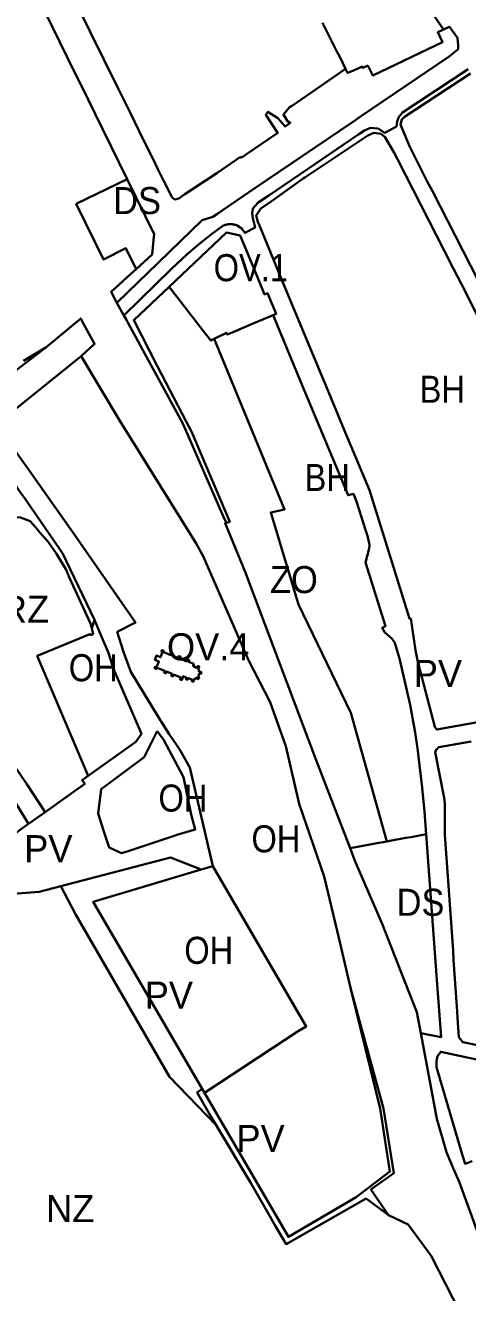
# Model space of a CAD drawing. Extents: x -650451 to -642268, y -1075216 to -1066610.
# Drawn here: x -647596 to -647351, y -1071706 to -1071004 of the extents above; entities that cross this region are included whole.
import ezdxf

# ---------------------------------------------------------------- set-up
doc = ezdxf.new("R2010")
doc.units = 0
doc.header["$LTSCALE"] = 6
doc.layers.add('1', color=7, linetype='Continuous', lineweight=35)
doc.layers.add('2', color=7, linetype='Continuous')
doc.layers.add('3', color=7, linetype='Continuous')

msp = doc.modelspace()

# ---------------------------------------------------------------- linework, layer by layer
at = {"layer": '1'}
for p, q in [((-647545.47, -1071157.86), (-647541.66, -1071164.75)), ((-647584.92, -1071182.54), (-647597.164, -1071189.857)), ((-647557.95, -1071333.44), (-647559.45, -1071338.18)), ((-647594.43, -1071446.543), (-647585.273, -1071440.044)), ((-647492.3, -1071470), (-647498.8, -1071471.94)), ((-647498.271, -1071593.544), (-647497.04, -1071595.66))]:
    msp.add_line(p, q, dxfattribs=at)
for points in [[(-647715.3, -1070769.09), (-647708.31, -1070783.21), (-647708.04, -1070783.07), (-647706.21, -1070786.87), (-647704.498, -1070790.24), (-647705.06, -1070790.51), (-647701.56, -1070797.79), (-647701.32, -1070798.28), (-647701.41, -1070798.33), (-647694.09, -1070813.56), (-647693.96, -1070813.49), (-647689.95, -1070821.13), (-647689.08, -1070820.64), (-647686.2, -1070826.54), (-647687.12, -1070826.94), (-647681.06, -1070839.75), (-647660.03, -1070856.69), (-647649.83, -1070864.82), (-647638.54, -1070887.82), (-647572.64, -1071022.41), (-647567.83, -1071032.07), (-647565.56, -1071036.69), (-647553.4, -1071061.35), (-647539.817, -1071089.199)], [(-647380.69, -1070978.37), (-647374.95, -1070991.15), (-647364.66, -1071006.25)], [(-647418.88, -1071028.01), (-647432.19, -1071037.23), (-647448.32, -1071048.39), (-647449.88, -1071049.31), (-647453.32, -1071053.37), (-647451.07, -1071057.07), (-647449.5, -1071057.92), (-647452.4, -1071060.03), (-647456.45, -1071055.44), (-647461.89, -1071051.91), (-647463.11, -1071053.53), (-647456.74, -1071063.18), (-647456.46, -1071063.6), (-647474.29, -1071075.65), (-647476.74, -1071077.3), (-647477.02, -1071076.88), (-647484.83, -1071082.15), (-647490.23, -1071085.8), (-647495.99, -1071089.71), (-647507.93, -1071097.59), (-647511.17, -1071099.94), (-647511.87, -1071100.11), (-647513.3, -1071100.42), (-647514.56, -1071099.74), (-647515.13, -1071098.97), (-647519.54, -1071090.25), (-647522.86, -1071083.58), (-647524.21, -1071080.84), (-647528.95, -1071071.14), (-647530.69, -1071067.54), (-647538.23, -1071052.19), (-647544.95, -1071038.52), (-647560.28, -1071007.46), (-647569.19, -1070989.36)], [(-647545.47, -1071157.86), (-647522.5, -1071135.41), (-647498.37, -1071111.95), (-647492.4, -1071110.08), (-647489.86, -1071108.38), (-647486.58, -1071106.19), (-647469.06, -1071094.28), (-647415.14, -1071057.61), (-647410.1, -1071054.18), (-647392.4, -1071042.15), (-647361.56, -1071021.28), (-647356.62, -1071017.06), (-647356.47, -1071014.98), (-647356.96, -1071010.82), (-647361.42, -1071004.71), (-647364.66, -1071006.25)], [(-647431.74, -1071002.56), (-647423.84, -1071018.04), (-647421.89, -1071021.82), (-647418.88, -1071028.01)], [(-647364.66, -1071006.25), (-647367.88, -1071007.78), (-647365.21, -1071013.19), (-647403.85, -1071031.66), (-647406.65, -1071026.24), (-647409.36, -1071027.52), (-647409.68, -1071026.85), (-647411.52, -1071027.64), (-647415.84, -1071029.49), (-647417.76, -1071030.31), (-647418.88, -1071028.01)], [(-647541.66, -1071164.75), (-647515.26, -1071138.89), (-647506.78, -1071130.92), (-647500.44, -1071125.54), (-647493.16, -1071119.77), (-647486.76, -1071115.13), (-647486, -1071114.76), (-647485.58, -1071114.61), (-647485.149, -1071114.479), (-647484.709, -1071114.368), (-647484.262, -1071114.278), (-647483.809, -1071114.209), (-647483.352, -1071114.162), (-647482.892, -1071114.138), (-647482.43, -1071114.137), (-647481.969, -1071114.158), (-647481.51, -1071114.201), (-647481.055, -1071114.267), (-647480.605, -1071114.355), (-647480.163, -1071114.464), (-647479.728, -1071114.593), (-647479.304, -1071114.742), (-647478.89, -1071114.91), (-647476.29, -1071116.6), (-647474.6, -1071119.05), (-647468.9, -1071115.97), (-647470.21, -1071110.77), (-647470.6, -1071108.01), (-647470.17, -1071105.39), (-647467.21, -1071102.22), (-647461.39, -1071098.23), (-647444.01, -1071086.37), (-647411.59, -1071064.32), (-647408.48, -1071062.15), (-647405.08, -1071060.75), (-647400.89, -1071061.05), (-647397.82, -1071063.08), (-647397.17, -1071063.56), (-647390.72, -1071059.94), (-647390.34, -1071057.27), (-647389.59, -1071055.1), (-647387.4, -1071052.29), (-647350.96, -1071028.22)], [(-647349.67, -1071030.64), (-647386.3, -1071054.58), (-647387.82, -1071056.14), (-647388.51, -1071058.82), (-647383.43, -1071070.95), (-647373.86, -1071090.07), (-647370.76, -1071095.88), (-647316.07, -1071202.91)], [(-647345.67, -1071390.27), (-647368.38, -1071394.35), (-647369.51, -1071392.87), (-647378.79, -1071356.84), (-647380.17, -1071350.38), (-647382.83, -1071332.82), (-647383.52, -1071332.79), (-647405.59, -1071261.54), (-647419.59, -1071228.11), (-647430.16, -1071202.64), (-647431.77, -1071198.79), (-647454.33, -1071144.64), (-647466.6, -1071114.88), (-647467.47, -1071112.93), (-647468.47, -1071109.42), (-647465.83, -1071105.54), (-647460.06, -1071101.57), (-647442.36, -1071088.82), (-647441.42, -1071088.2), (-647406.52, -1071065.05), (-647403.15, -1071063.6), (-647399.31, -1071064.09), (-647397.07, -1071065.71), (-647392.21, -1071074.16), (-647389.98, -1071078.54), (-647364.3, -1071128.77), (-647359.04, -1071138.83), (-647354.68, -1071147.49), (-647339.01, -1071178.6)], [(-647534.851, -1071139.015), (-647540.48, -1071127.55), (-647553.01, -1071133.68), (-647568.01, -1071102.98), (-647539.817, -1071089.199)], [(-647534.851, -1071139.015), (-647526.04, -1071130.94), (-647525.1, -1071121.25), (-647524.95, -1071119.68), (-647539.817, -1071089.199)], [(-647516.65, -1071148.87), (-647484.84, -1071118.8), (-647477.3, -1071120.38), (-647469.39, -1071139.47), (-647463.76, -1071153.08), (-647462.13, -1071152.39), (-647457.39, -1071163.94), (-647458.99, -1071164.62)], [(-647545.47, -1071157.86), (-647548.7, -1071151.72), (-647538.02, -1071141.92), (-647534.851, -1071139.015)], [(-647484.9, -1071279.73), (-647483.04, -1071279.11), (-647504.27, -1071229.17), (-647507.14, -1071223.62), (-647523.09, -1071193.08), (-647536.2, -1071167.35), (-647516.65, -1071148.87)], [(-647491.56, -1071177.65), (-647493.58, -1071178.64), (-647497.03, -1071174.18), (-647516.65, -1071148.87)], [(-647584.92, -1071182.54), (-647565.54, -1071166.39), (-647564.11, -1071169.03), (-647559.87, -1071176.88), (-647557.9, -1071180.51), (-647565.22, -1071187.4)], [(-647541.66, -1071164.75), (-647540.27, -1071167.26), (-647539.25, -1071169.11), (-647508.98, -1071224.74), (-647485.9, -1071277.7), (-647484.9, -1071279.73)], [(-647458.99, -1071164.62), (-647469.69, -1071169.11), (-647475.25, -1071171.44), (-647480.78, -1071173.77), (-647484.47, -1071175.32), (-647484.85, -1071174.37), (-647491.56, -1071177.65)], [(-647458.99, -1071164.62), (-647443.1, -1071203.11), (-647417.48, -1071264.44), (-647414.45, -1071263.72), (-647412.92, -1071267.86), (-647407.95, -1071282.98), (-647406.83, -1071286.84), (-647405.81, -1071290.99), (-647405.67, -1071292.42), (-647405.81, -1071293.71), (-647406, -1071294.73), (-647407.77, -1071301.63), (-647396.78, -1071337.03), (-647398.69, -1071338), (-647397.07, -1071340.54), (-647393.18, -1071343.93), (-647391.57, -1071346.17), (-647389.7, -1071352.48), (-647389.02, -1071354.89), (-647383.11, -1071380.7), (-647381.2, -1071391.04), (-647380.88, -1071392.81), (-647380.41, -1071395.94), (-647378.88, -1071406.02), (-647378.64, -1071407.86), (-647376.66, -1071424.88), (-647376.42, -1071426.67), (-647375.13, -1071439.72), (-647374.2, -1071452.36)], [(-647668.226, -1071237.57), (-647661.99, -1071236.62), (-647658.78, -1071235.63), (-647651.93, -1071233.57), (-647635.17, -1071224.18), (-647613.09, -1071204.33), (-647610.4, -1071201.91), (-647584.92, -1071182.54)], [(-647396.02, -1071456.32), (-647415.97, -1071385.01), (-647445, -1071324.99), (-647460.28, -1071274.02), (-647452.69, -1071272.32), (-647491.56, -1071177.65)], [(-647605.5, -1071220.17), (-647603.35, -1071218), (-647565.22, -1071187.4)], [(-647416, -1071538.22), (-647422.68, -1071509.72), (-647430.76, -1071475.77), (-647444.55, -1071435.57), (-647451.96, -1071403.5), (-647460.71, -1071379.08), (-647472.58, -1071355.91), (-647487.02, -1071322.83), (-647497.77, -1071298.19), (-647501.59, -1071291.15), (-647504.01, -1071287.34), (-647543.83, -1071223.23), (-647565.22, -1071187.4)], [(-647605.5, -1071220.17), (-647607.11, -1071222.78), (-647608.04, -1071225.7), (-647608.09, -1071228.7), (-647607.49, -1071231.68), (-647592.65, -1071252.72), (-647568.83, -1071286.51), (-647535.19, -1071335), (-647545.42, -1071340.16), (-647542.01, -1071350.72), (-647541.66, -1071351.76), (-647537.84, -1071362.41), (-647521.32, -1071389.29), (-647521.06, -1071389.76), (-647516.55, -1071396.79), (-647510.84, -1071405.24), (-647505.11, -1071415.37), (-647492.3, -1071470)], [(-647557.95, -1071333.44), (-647575.61, -1071296.52), (-647596.91, -1071265.68), (-647598.99, -1071262.68), (-647600.93, -1071259.86), (-647601.37, -1071259.23), (-647604.8, -1071254.95), (-647607.21, -1071251.94), (-647611.46, -1071246.64), (-647611.07, -1071246.43), (-647612.8, -1071244.96), (-647620.21, -1071238.7), (-647626.92, -1071241.32), (-647628.88, -1071242.01), (-647629.84, -1071242.36), (-647640.98, -1071246.3), (-647646.11, -1071248.11), (-647651.83, -1071250.14), (-647662.68, -1071253.98), (-647673.55, -1071257.83), (-647679.2, -1071259.81), (-647680.57, -1071260.28), (-647689.61, -1071263.51)], [(-647559.45, -1071338.18), (-647560.08, -1071335.6), (-647565.43, -1071323.92), (-647571.68, -1071310.25), (-647573.87, -1071305.47), (-647578.87, -1071296.87), (-647583.66, -1071290.33), (-647588.2, -1071285.06), (-647590.57, -1071282.13), (-647593.59, -1071278.74), (-647598.84, -1071276.77), (-647601.82, -1071276.61), (-647607.25, -1071278.65), (-647621.64, -1071294.26), (-647642.12, -1071312.63), (-647645.94, -1071311.85), (-647653.22, -1071310.36), (-647660.39, -1071318.38), (-647666.629, -1071325.351)], [(-647484.9, -1071279.73), (-647485.58, -1071279.95), (-647474.15, -1071307.9), (-647471.19, -1071315.76), (-647435.19, -1071411.22), (-647416.42, -1071460.03)], [(-647557.95, -1071333.44), (-647554.18, -1071342.3), (-647550.12, -1071351.87), (-647547.43, -1071360.71), (-647531.93, -1071396.68), (-647534.94, -1071401.09), (-647561.38, -1071419.94)], [(-647559.45, -1071338.18), (-647558.66, -1071341.37), (-647560.16, -1071341.99), (-647560.46, -1071341.39), (-647589.03, -1071353.19), (-647589.57, -1071353.41), (-647561.38, -1071419.94)], [(-647701.415, -1071480.15), (-647699.767, -1071481.617), (-647625.428, -1071403.267), (-647612.269, -1071419.742), (-647605.292, -1071428.816), (-647594.43, -1071446.543)], [(-647335.88, -1071571.31), (-647353.95, -1071567.53), (-647356.2, -1071564.75), (-647356.91, -1071554.11), (-647357.15, -1071550.44), (-647359.03, -1071522.12), (-647359.38, -1071516.88), (-647363.86, -1071452.66), (-647363.83, -1071435.52), (-647364.26, -1071432.14), (-647369.34, -1071406.92), (-647368.74, -1071405.48), (-647367.18, -1071404.12), (-647349.29, -1071400.99)], [(-647585.273, -1071440.044), (-647595.335, -1071424.564), (-647603.9, -1071412.1)], [(-647585.273, -1071440.044), (-647572.79, -1071431.18), (-647563.33, -1071424.47), (-647564.81, -1071422.45), (-647561.38, -1071419.94)], [(-647594.43, -1071446.543), (-647597.54, -1071448.75), (-647611.82, -1071459.38), (-647626.7, -1071470.46), (-647642.45, -1071482.62), (-647655.517, -1071492.465), (-647656.27, -1071493.04), (-647674.28, -1071506.59), (-647676.51, -1071504.34), (-647764.23, -1071571.01), (-647771.717, -1071576.551)], [(-647416.42, -1071460.03), (-647412.36, -1071459.29), (-647409.26, -1071458.73), (-647403.35, -1071457.65), (-647400.4, -1071457.12), (-647398.057, -1071456.69), (-647396.02, -1071456.32)], [(-647374.2, -1071452.36), (-647379.73, -1071453.36), (-647382.59, -1071453.88), (-647385.49, -1071454.41), (-647388.54, -1071454.96), (-647394.45, -1071456.04), (-647396.02, -1071456.32)], [(-647374.2, -1071452.36), (-647368.26, -1071532.99), (-647365.91, -1071564.81), (-647377.13, -1071562.56)], [(-647377.13, -1071562.56), (-647379.49, -1071550.89), (-647388.29, -1071528.41), (-647398.64, -1071501.96), (-647413.54, -1071467.53), (-647416.42, -1071460.03)], [(-647498.8, -1071471.94), (-647515.87, -1071465.25), (-647576.471, -1071481.091)], [(-647497.04, -1071595.66), (-647445.11, -1071561.48), (-647440.67, -1071558.93), (-647492.3, -1071470)], [(-647498.271, -1071593.544), (-647558.654, -1071489.738), (-647498.8, -1071471.94)], [(-647576.471, -1071481.091), (-647588.48, -1071484.23), (-647632, -1071487.54), (-647639.66, -1071490.78), (-647650.97, -1071499.11), (-647658.2, -1071504.43), (-647694.65, -1071531.5), (-647756.17, -1071577.89), (-647767.07, -1071589.67), (-647771.408, -1071602.414)], [(-647576.471, -1071481.091), (-647568.35, -1071496.656), (-647516.376, -1071586.89), (-647490.561, -1071613.609)], [(-647497.04, -1071595.66), (-647450.58, -1071675.53), (-647413.06, -1071653.58), (-647394.33, -1071639.33), (-647399.81, -1071604.31), (-647416, -1071538.22)], [(-647395.07, -1071663.45), (-647404.81, -1071649.36), (-647392.2, -1071640.14), (-647397.94, -1071604.35), (-647416, -1071538.22)], [(-647286.89, -1071767.67), (-647288.23, -1071768.15), (-647312.86, -1071737.11), (-647344.03, -1071677.91), (-647355.85, -1071645.37), (-647359.23, -1071637.45), (-647363.05, -1071628.52), (-647368.43, -1071610.03), (-647375.33, -1071572.37), (-647377.13, -1071562.56)], [(-647334.14, -1071579.76), (-647366.15, -1071572.96), (-647367.99, -1071575.36), (-647368.58, -1071577.93), (-647368.58, -1071581.54), (-647358.36, -1071616.1), (-647357.82, -1071617.94), (-647354.11, -1071630.46), (-647352.75, -1071635.04), (-647348.75, -1071633.55)], [(-647498.271, -1071593.544), (-647501.11, -1071595.45), (-647493.6, -1071608.5), (-647490.561, -1071613.609)], [(-647395.07, -1071663.45), (-647407.49, -1071654.3), (-647451.72, -1071679.52), (-647457.62, -1071669.57), (-647463.05, -1071660.13), (-647471.62, -1071645.45), (-647490.561, -1071613.609)], [(-647351.64, -1071725.05), (-647371.48, -1071686.13), (-647384.28, -1071668.72), (-647395.07, -1071663.45)]]:
    msp.add_lwpolyline(points, dxfattribs=at)
for points in [[(-647523.37, -1071359.34), (-647522.28, -1071356.63), (-647524.47, -1071355.64), (-647523.5, -1071353.25), (-647521.31, -1071354.19), (-647520.37, -1071351.85), (-647520.85, -1071350.56), (-647519.95, -1071350.22), (-647519.45, -1071351.47), (-647515.6, -1071353), (-647515.19, -1071352.03), (-647514.29, -1071352.36), (-647514.67, -1071353.39), (-647511.51, -1071354.65), (-647511.1, -1071353.63), (-647510.18, -1071354.02), (-647510.59, -1071355.01), (-647506.75, -1071356.51), (-647506.38, -1071355.53), (-647505.45, -1071355.86), (-647505.79, -1071356.81), (-647502.94, -1071357.95), (-647503.33, -1071358.95), (-647501.43, -1071360.01), (-647500.55, -1071359.01), (-647499.86, -1071359.67), (-647500.57, -1071360.36), (-647499.87, -1071362.28), (-647498.8, -1071362.34), (-647498.84, -1071363.29), (-647499.81, -1071363.3), (-647500.55, -1071365.1), (-647499.87, -1071365.69), (-647500.51, -1071366.44), (-647501.29, -1071365.73), (-647503.01, -1071366.67), (-647502.98, -1071367.63), (-647503.96, -1071367.67), (-647503.99, -1071366.66), (-647506.04, -1071365.82), (-647506.47, -1071366.76), (-647507.29, -1071366.45), (-647506.94, -1071365.49), (-647508.73, -1071364.78), (-647509.58, -1071366.9), (-647510.48, -1071366.51), (-647510.06, -1071365.53), (-647514.09, -1071363.85), (-647514.5, -1071364.86), (-647515.39, -1071364.49), (-647514.97, -1071363.49), (-647518.1, -1071362.12), (-647518.59, -1071363.1), (-647519.46, -1071362.76), (-647519.05, -1071361.79), (-647522.92, -1071360.2), (-647524.28, -1071360.72), (-647524.63, -1071359.81)], [(-647523.23, -1071395.17), (-647519.72, -1071399.92), (-647508.69, -1071420.74), (-647504.34, -1071441.33), (-647502.09, -1071449.64), (-647512.23, -1071452.75), (-647512.62, -1071452.86), (-647539.31, -1071461.66), (-647543.05, -1071462.76), (-647549.73, -1071459.73), (-647552.85, -1071450.23), (-647555.92, -1071440.87), (-647554.16, -1071427.31), (-647530.41, -1071409.54)]]:
    msp.add_lwpolyline(points, close=True, dxfattribs=at)

# ---------------------------------------------------------------- texts
at = {"layer": '2'}
for s, width, p in [('OV.1', 0.9, (-647491.932, -1071145.771)), ('BH', 0.9, (-647377.881, -1071213.173)), ('BH', 0.9, (-647441.596, -1071262.071)), ('ZO', 0.95, (-647460.733, -1071318.693)), ('OH', 0.9, (-647572.151, -1071367.535)), ('OH', 0.9, (-647522.5, -1071439.789)), ('OH', 0.9, (-647470.996, -1071462.391)), ('DS', 0.95, (-647390.62, -1071497.571))]:
    msp.add_text(s, height=15, dxfattribs=dict(at, width=width)).set_placement(p)
for s, p in [('RZ', (-647609.765, -1071335.106)), ('OV.4', (-647517.777, -1071355.955)), ('PV', (-647381.139, -1071370.729)), ('PV', (-647596.861, -1071467.853)), ('PV', (-647479.33, -1071628.472)), ('NZ', (-647584.747, -1071667.388))]:
    msp.add_text(s, height=15, dxfattribs=at).set_placement(p)
at = {"layer": '3'}
for s, width, p in [('DS', 0.95, (-647547.573, -1071108.584)), ('OH', 0.9, (-647508.194, -1071524.191))]:
    msp.add_text(s, height=15, dxfattribs=dict(at, width=width)).set_placement(p)
msp.add_text('PV', height=15, dxfattribs=at).set_placement((-647530.106, -1071549.044))

doc.saveas('drawing.dxf')
